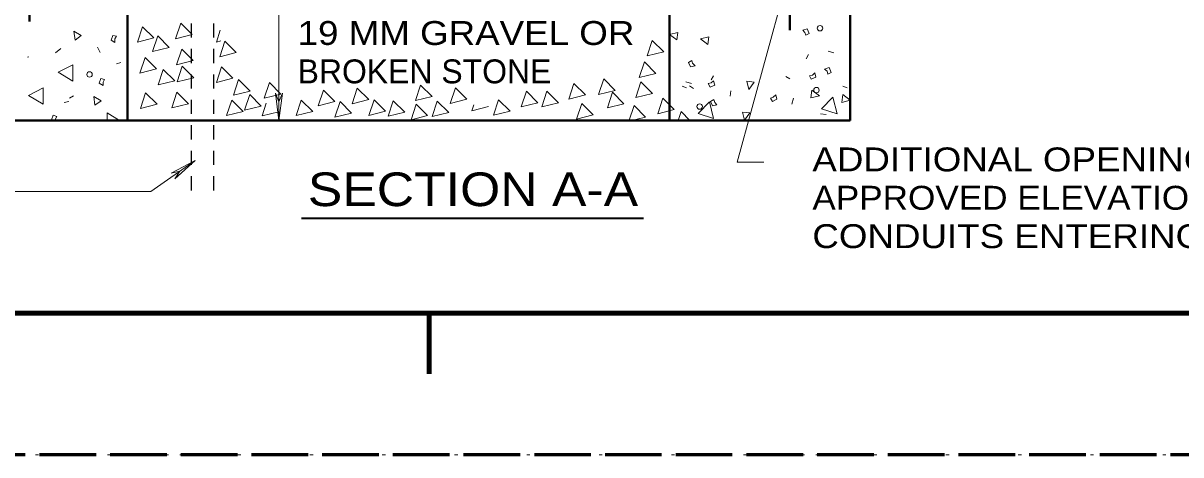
# Model space of a CAD drawing. Extents: x 312583 to 312854, y 144419 to 144597.
# Drawn here: x 312714.43 to 312751.27, y 144418.58 to 144432.31 of the extents above; entities that cross this region are included whole.
import ezdxf
from ezdxf.enums import TextEntityAlignment as Align

# ---------------------------------------------------------------- set-up
doc = ezdxf.new("R2010")
doc.units = 0
doc.header["$LTSCALE"] = 0.3
for name, pattern in [('DOTTED', [1.5, 0.3, -1.2]), ('LONG_DASHED', [7.5, 6, -1.5]), ('MEDIUM_DASHED', [4.5, 3, -1.5]), ('SHORT_DASHED', [2.7, 1.5, -1.2])]:
    doc.linetypes.add(name, pattern=pattern)
doc.layers.add('1', color=7, linetype='Continuous', lineweight=13)
doc.layers.add('63', color=7, linetype='DOTTED', lineweight=13)

msp = doc.modelspace()

# ---------------------------------------------------------------- linework, layer by layer
at = {"layer": '1', "lineweight": 40}
for p, q in [((312717.7513, 144471.1459), (312717.7513, 144429.2169)), ((312735.0013, 144435.8562), (312735.0013, 144429.2169)), ((312740.7513, 144435.8562), (312740.7513, 144429.2169)), ((312697.3886, 144429.2169), (312740.7513, 144429.2169))]:
    msp.add_line(p, q, dxfattribs=at)
at = {"layer": '1', "linetype": 'MEDIUM_DASHED', "lineweight": 40}
for p, q in [((312714.6386, 144469.7122), (312714.6386, 144432.0919)), ((312738.8346, 144435.4652), (312738.8346, 144432.0919))]:
    msp.add_line(p, q, dxfattribs=at)
at = {"layer": '1'}
for p, q in [((312722.5736, 144452.2169), (312722.5736, 144429.2169)), ((312739.6013, 144436.7992), (312737.1556, 144427.8905)), ((312714.5849, 144431.2255), (312714.6079, 144431.2409)), ((312714.5849, 144431.2409), (312714.5849, 144431.2255)), ((312715.6353, 144431.5015), (312715.4589, 144431.3712)), ((312716.7929, 144431.5475), (312716.8773, 144431.3789)), ((312739.4249, 144431.3099), (312739.3559, 144431.1719)), ((312740.2299, 144431.3635), (312740.0459, 144431.4249)), ((312717.3986, 144431.0185), (312717.5443, 144431.0569)), ((312736.3276, 144430.5049), (312736.3966, 144430.6352)), ((312738.8346, 144430.5432), (312738.7043, 144430.6199)), ((312717.7436, 144430.2749), (312717.7436, 144430.3822)), ((312735.5456, 144430.2595), (312735.4076, 144430.3055)), ((312735.5226, 144430.4435), (312735.7066, 144430.3899)), ((312735.7603, 144430.2365), (312735.6376, 144430.3209)), ((312736.9333, 144429.9912), (312736.9563, 144430.1599)), ((312740.6593, 144430.2595), (312740.5213, 144430.3055)), ((312715.7349, 144429.7919), (312715.8806, 144429.8225)), ((312715.9036, 144429.9299), (312716.0339, 144429.9989)), ((312722.4663, 144430.0832), (312722.5736, 144429.8072)), ((312722.5736, 144429.2169), (312722.4663, 144430.0832)), ((312722.6809, 144430.0832), (312722.5736, 144429.8072)), ((312722.5736, 144429.2169), (312722.6809, 144430.0832)), ((312738.8959, 144429.7382), (312738.9496, 144429.9222)), ((312717.1073, 144429.4545), (312717.1073, 144429.2169)), ((312717.4983, 144429.2169), (312717.1073, 144429.4545)), ((312739.9846, 144429.4085), (312739.8083, 144429.4315)), ((312715.4589, 144429.2169), (312715.4589, 144429.2705)), ((312718.4949, 144426.9629), (312719.9056, 144427.9442)), ((312719.9056, 144427.9442), (312719.1389, 144427.5379)), ((312719.9056, 144427.9442), (312719.2616, 144427.3615)), ((312719.1389, 144427.5379), (312719.4226, 144427.6069)), ((312719.2616, 144427.3615), (312719.4226, 144427.6069)), ((312737.1556, 144427.8905), (312737.9989, 144427.8905)), ((312694.5903, 144426.9629), (312718.4949, 144426.9629))]:
    msp.add_line(p, q, dxfattribs=at)
at = {"layer": '1', "linetype": 'SHORT_DASHED', "lineweight": 25}
for p, q in [((312719.7906, 144426.9935), (312719.7906, 144434.9669)), ((312720.5036, 144426.9935), (312720.5036, 144434.9669))]:
    msp.add_line(p, q, dxfattribs=at)
at = {"layer": '1', "lineweight": 35}
msp.add_line((312723.2944, 144426.1084), (312734.1737, 144426.1084), dxfattribs=at)
at = {"layer": '1', "lineweight": 158}
for p, q in [((312616.5, 144423.0846), (312849, 144423.0846)), ((312727.35, 144421.1646), (312727.35, 144423.0846))]:
    msp.add_line(p, q, dxfattribs=at)
at = {"layer": '1', "linetype": 'LONG_DASHED', "lineweight": 60}
msp.add_line((312851.75, 144418.5846), (312583.526, 144418.5846), dxfattribs=at)
at = {"layer": '1'}
for points in [[(312716.0876, 144431.7699), (312716.2793, 144431.9155), (312716.0493, 144432.0535)], [(312718.5946, 144431.8389), (312718.2343, 144432.1992), (312718.0656, 144431.7085)], [(312719.8136, 144431.9462), (312719.4456, 144432.3065), (312719.2846, 144431.8159)], [(312735.2313, 144431.7775), (312735.2696, 144432.0152), (312735.0013, 144431.9462)], [(312739.3099, 144432.0152), (312739.3406, 144431.9309), (312739.4479, 144431.9845), (312739.3789, 144432.1302), (312739.2409, 144432.0919)], [(312717.3526, 144431.8082), (312717.4063, 144431.8925), (312717.2836, 144431.9232), (312717.2299, 144431.7699), (312717.3526, 144431.7009)], [(312719.0776, 144431.5399), (312718.7173, 144431.9079), (312718.5486, 144431.4095)], [(312721.2154, 144431.3745), (312720.8551, 144431.7425), (312720.6864, 144431.2441)], [(312734.8173, 144431.4019), (312734.4493, 144431.7622), (312734.2883, 144431.2715)], [(312736.2203, 144431.6319), (312736.2509, 144431.8772), (312735.9826, 144431.8082)], [(312718.6789, 144430.8575), (312718.3109, 144431.2179), (312718.1499, 144430.7195)], [(312719.8443, 144431.1182), (312719.4763, 144431.4862), (312719.3153, 144430.9879)], [(312716.0109, 144430.4665), (312716.0109, 144430.9879), (312715.5433, 144430.7502)], [(312719.8596, 144430.5739), (312719.4916, 144430.9419), (312719.3306, 144430.4435)], [(312721.1093, 144430.5585), (312720.7413, 144430.9189), (312720.5803, 144430.4282)], [(312734.5643, 144430.7119), (312734.2039, 144431.0799), (312734.0353, 144430.5815)], [(312735.7373, 144431.0339), (312735.7143, 144431.1259), (312735.6069, 144431.0645), (312735.6683, 144430.9189), (312735.8139, 144430.9572)], [(312740.0153, 144430.7809), (312740.0383, 144430.6889), (312740.1456, 144430.7425), (312740.0843, 144430.8959), (312739.9386, 144430.8499)], [(312716.9769, 144430.4359), (312717.0229, 144430.5202), (312716.9079, 144430.5509), (312716.8466, 144430.3975), (312716.9769, 144430.3285)], [(312719.2539, 144430.4819), (312718.8859, 144430.8422), (312718.7249, 144430.3515)], [(312721.6536, 144430.1522), (312721.2856, 144430.5202), (312721.1246, 144430.0219)], [(312733.2686, 144430.1675), (312732.9083, 144430.5355), (312732.7396, 144430.0372)], [(312736.3276, 144430.4129), (312736.2356, 144430.3899), (312736.2969, 144430.2749), (312736.4426, 144430.3439), (312736.4043, 144430.4819)], [(312739.5476, 144430.6582), (312739.4556, 144430.6352), (312739.5093, 144430.5279), (312739.6626, 144430.5892), (312739.6243, 144430.7349)], [(312715.0679, 144429.7305), (312715.0679, 144430.2519), (312714.6003, 144430.0142)], [(312719.6909, 144429.7459), (312719.3229, 144430.1139), (312719.1619, 144429.6155)], [(312722.6349, 144430.0525), (312722.2746, 144430.4205), (312722.1059, 144429.9222)], [(312724.3538, 144429.8171), (312723.9858, 144430.1775), (312723.8248, 144429.6868)], [(312725.4286, 144429.8785), (312725.0606, 144430.2465), (312724.8996, 144429.7481)], [(312727.4496, 144429.9835), (312727.0816, 144430.3439), (312726.9206, 144429.8532)], [(312728.5536, 144429.8915), (312728.1856, 144430.2519), (312728.0246, 144429.7612)], [(312730.8076, 144429.7765), (312730.4473, 144430.1445), (312730.2786, 144429.6462)], [(312731.4669, 144429.7765), (312731.0989, 144430.1445), (312730.9379, 144429.6462)], [(312732.3256, 144430.0295), (312731.9576, 144430.3899), (312731.7966, 144429.8992)], [(312733.5523, 144429.7459), (312733.1919, 144430.1139), (312733.0233, 144429.6155)], [(312734.4569, 144430.0755), (312734.0889, 144430.4435), (312733.9279, 144429.9452)], [(312737.6999, 144430.4359), (312737.4623, 144430.4665), (312737.5313, 144430.2059)], [(312739.5323, 144430.1752), (312739.5016, 144429.9375), (312739.7699, 144429.9989)], [(312716.7163, 144429.6999), (312716.9156, 144429.8455), (312716.6779, 144429.9835)], [(312718.6943, 144429.7305), (312718.3263, 144430.0985), (312718.1653, 144429.6002)], [(312721.4313, 144429.5005), (312721.0709, 144429.8609), (312720.9023, 144429.3702)], [(312722.0063, 144429.6692), (312721.6459, 144430.0372), (312721.4773, 144429.5389)], [(312723.6469, 144429.5005), (312723.2789, 144429.8609), (312723.1179, 144429.3702)], [(312724.8821, 144429.4522), (312724.5217, 144429.8202), (312724.3531, 144429.3219)], [(312725.9614, 144429.5082), (312725.6011, 144429.8762), (312725.4324, 144429.3778)], [(312726.5756, 144429.4852), (312726.2076, 144429.8455), (312726.0466, 144429.3549)], [(312727.9786, 144429.4699), (312727.6106, 144429.8302), (312727.4496, 144429.3395)], [(312729.9259, 144429.5159), (312729.5579, 144429.8762), (312729.3969, 144429.3855)], [(312732.5709, 144429.3932), (312732.2106, 144429.7535), (312732.0419, 144429.2552)], [(312735.1546, 144429.5619), (312734.7943, 144429.9222), (312734.6256, 144429.4315)], [(312736.2739, 144429.8072), (312735.9136, 144429.4392), (312736.4043, 144429.2782)], [(312736.4426, 144429.7919), (312736.4119, 144429.8839), (312736.3046, 144429.8225), (312736.3736, 144429.6769), (312736.5116, 144429.7152)], [(312738.3056, 144429.9529), (312738.2136, 144429.9299), (312738.2749, 144429.8225), (312738.4206, 144429.8915), (312738.3823, 144430.0295)], [(312740.1993, 144429.9529), (312739.8389, 144429.5849), (312740.3373, 144429.4239)], [(312740.5213, 144430.0372), (312740.4829, 144429.7919), (312740.7513, 144429.8609)], [(312727.3039, 144429.3779), (312726.9436, 144429.7382), (312726.7749, 144429.2399)], [(312734.2346, 144429.3242), (312733.8743, 144429.6922), (312733.7056, 144429.1939)], [(312737.5619, 144429.4545), (312737.3243, 144429.4852), (312737.3856, 144429.2245)]]:
    msp.add_lwpolyline(points, close=True, dxfattribs=at)
for points in [[(312720.7029, 144432.0842), (312720.5803, 144431.7085), (312720.7259, 144431.7469)], [(312722.1673, 144429.7689), (312722.0369, 144429.3625), (312722.5659, 144429.4929)], [(312715.4589, 144429.2705), (312715.5049, 144429.3472), (312715.3899, 144429.3855), (312715.3286, 144429.2322), (312715.3516, 144429.2169)], [(312728.7759, 144429.7152), (312728.7146, 144429.5235), (312729.2436, 144429.6615)], [(312735.6453, 144429.2169), (312735.3693, 144429.5005), (312735.2773, 144429.2169)]]:
    msp.add_lwpolyline(points, dxfattribs=at)
for centre in [(312739.7916, 144432.1511), (312716.5435, 144430.6804), (312739.6776, 144430.1804), (312735.9609, 144429.6599)]:
    msp.add_circle(centre, 0.0865, dxfattribs=at)
at = {"layer": '63'}
msp.add_lwpolyline([(312601.2, 144418.5846), (312853.5, 144418.5846), (312853.5, 144596.7846)], dxfattribs=at)

# ---------------------------------------------------------------- texts
at = {"layer": '1'}
for s, width, p in [('19 MM GRAVEL OR', 1.15, (312723.1664, 144431.6176)), ('ADDITIONAL OPENINGS SHALL BE PROVIDED AT', 1.15, (312739.548, 144427.5981)), ('APPROVED ELEVATIONS FOR UNDER ROADWAY', 1.1, (312739.548, 144426.3781)), ('CONDUITS ENTERING JUNCTION BOX TYPICAL.', 1.15, (312739.548, 144425.1581))]:
    msp.add_text(s, height=0.76, dxfattribs=dict(at, width=width)).set_placement(p)
msp.add_text('BROKEN STONE', height=0.76, dxfattribs=at).set_placement((312723.1664, 144430.3976))
at = {"layer": '1', "width": 1.15}
msp.add_text('SECTION A-A', height=1.07, dxfattribs=at).set_placement((312728.7477, 144426.4929), align=Align.CENTER)

doc.saveas('drawing.dxf')
